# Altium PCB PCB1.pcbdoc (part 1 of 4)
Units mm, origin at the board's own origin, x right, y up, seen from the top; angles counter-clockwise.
Board outline 77.9 x 107.7 mm, 4 copper layers (Top Layer, Inner1, Inner2, Bottom Layer); 106 components, 123 nets, 650 pads, 272 vias.
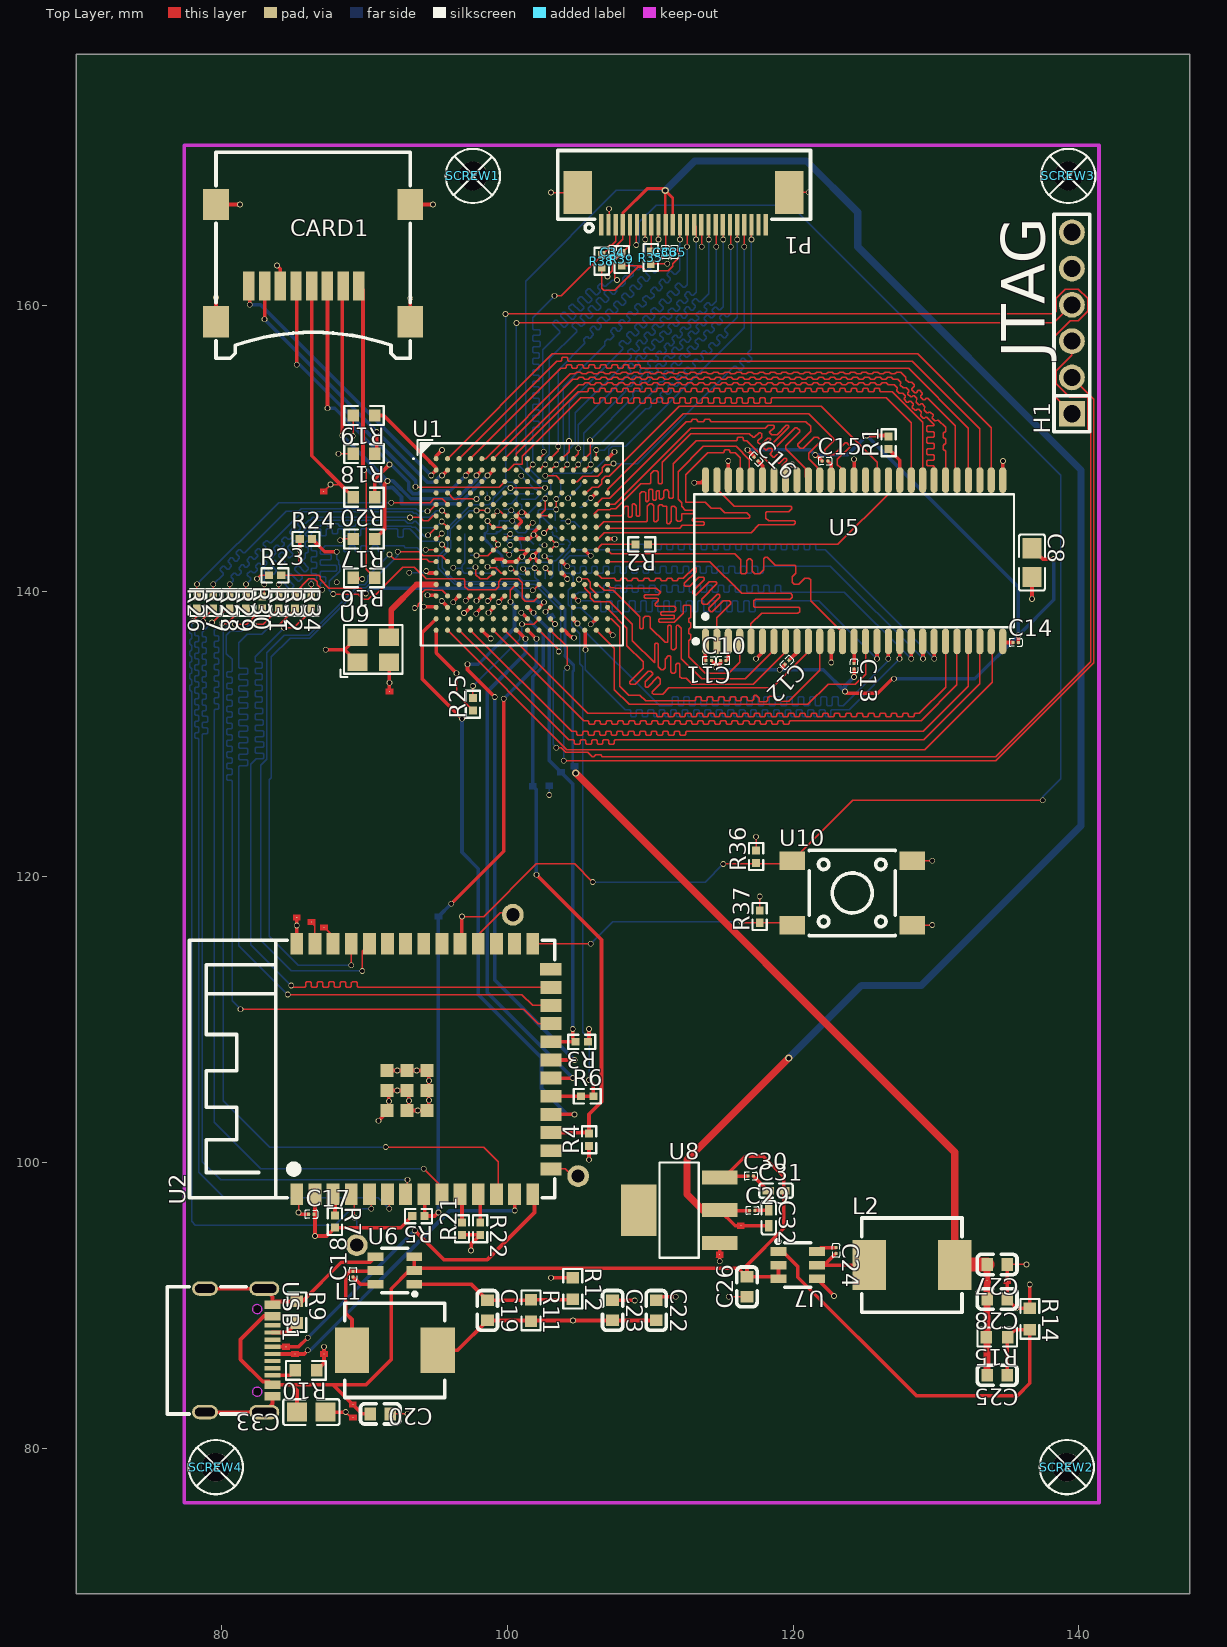
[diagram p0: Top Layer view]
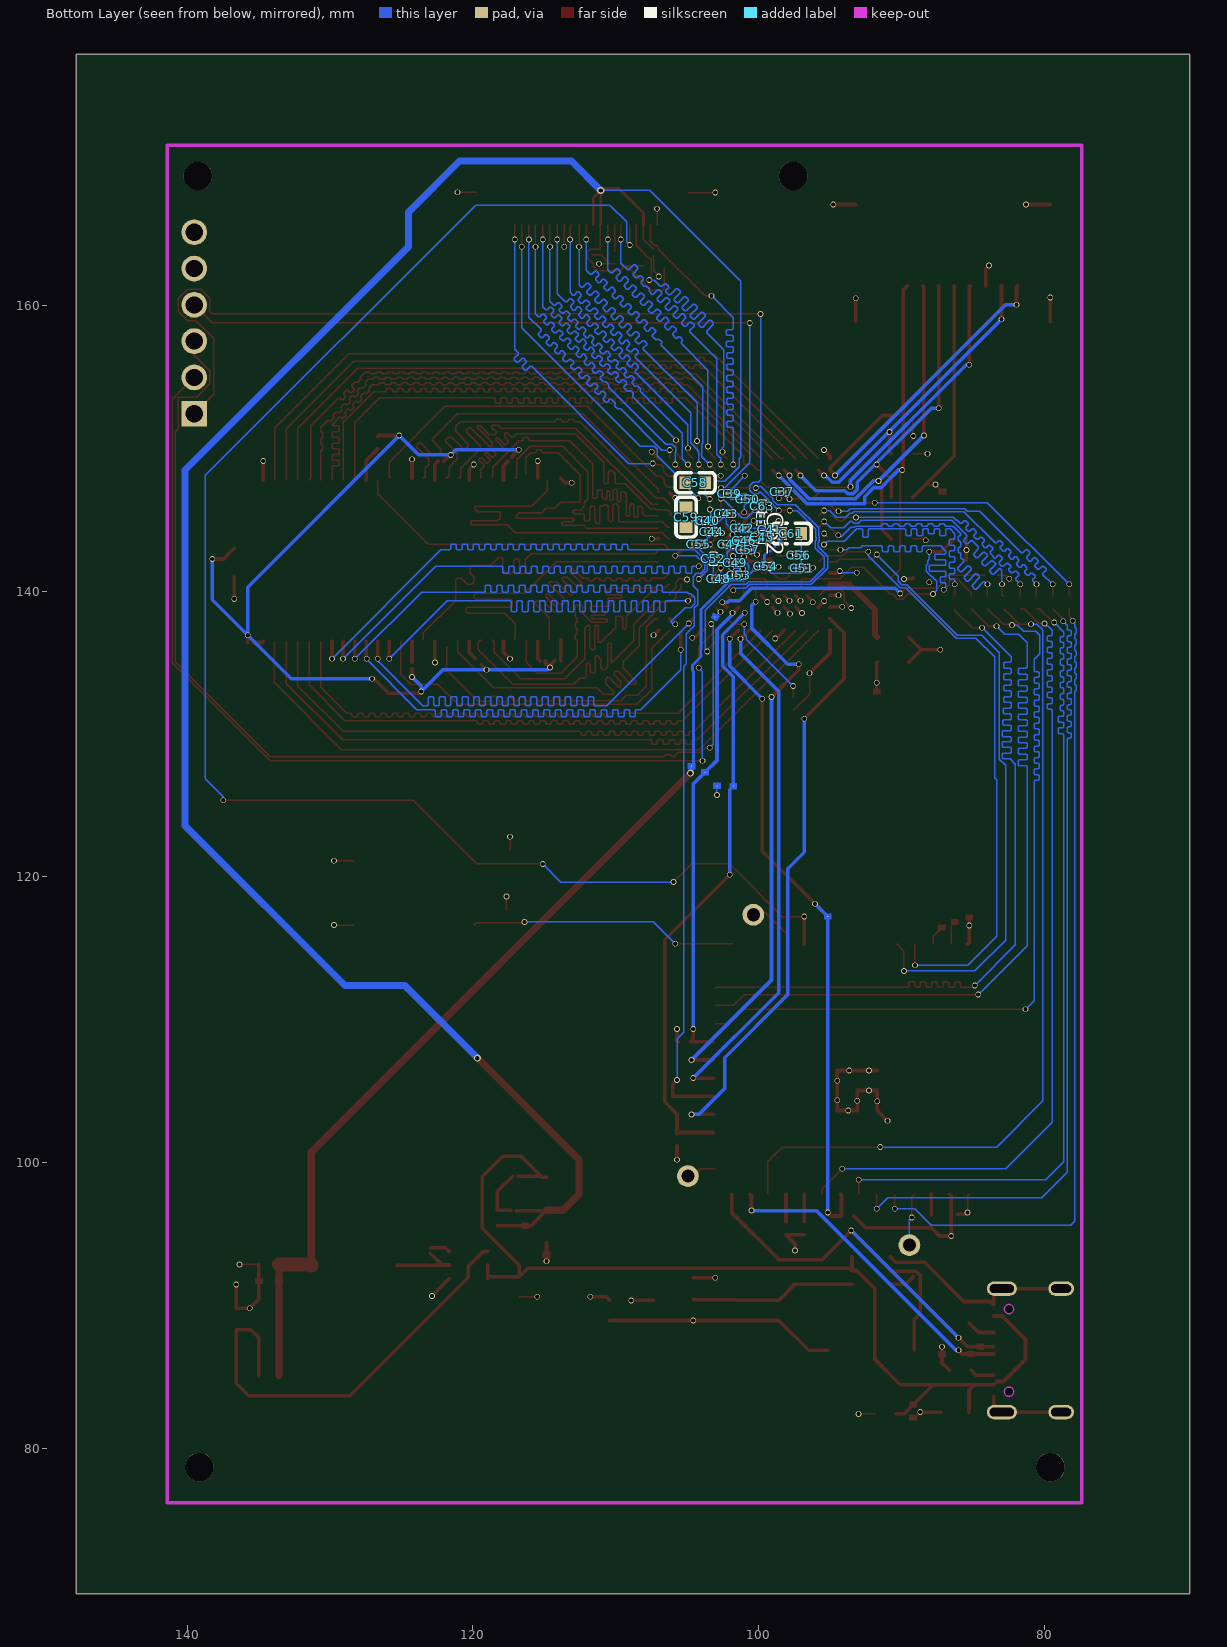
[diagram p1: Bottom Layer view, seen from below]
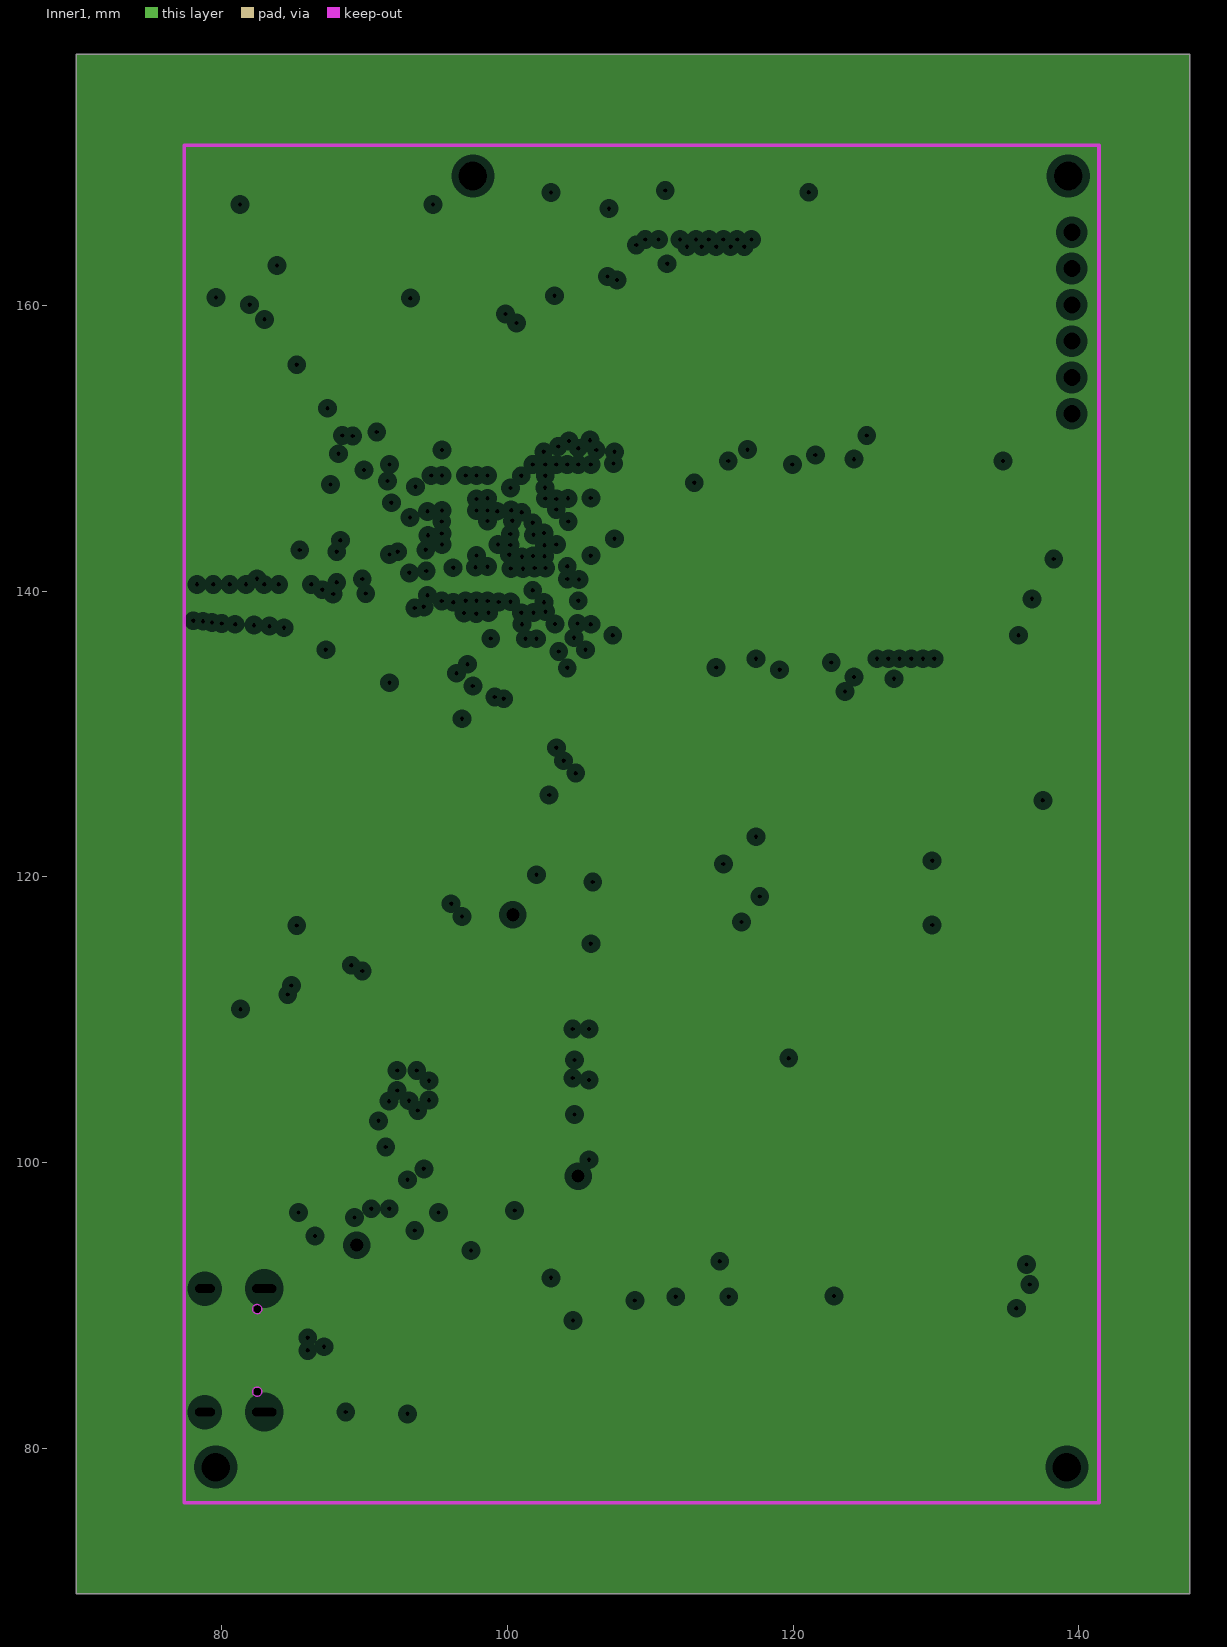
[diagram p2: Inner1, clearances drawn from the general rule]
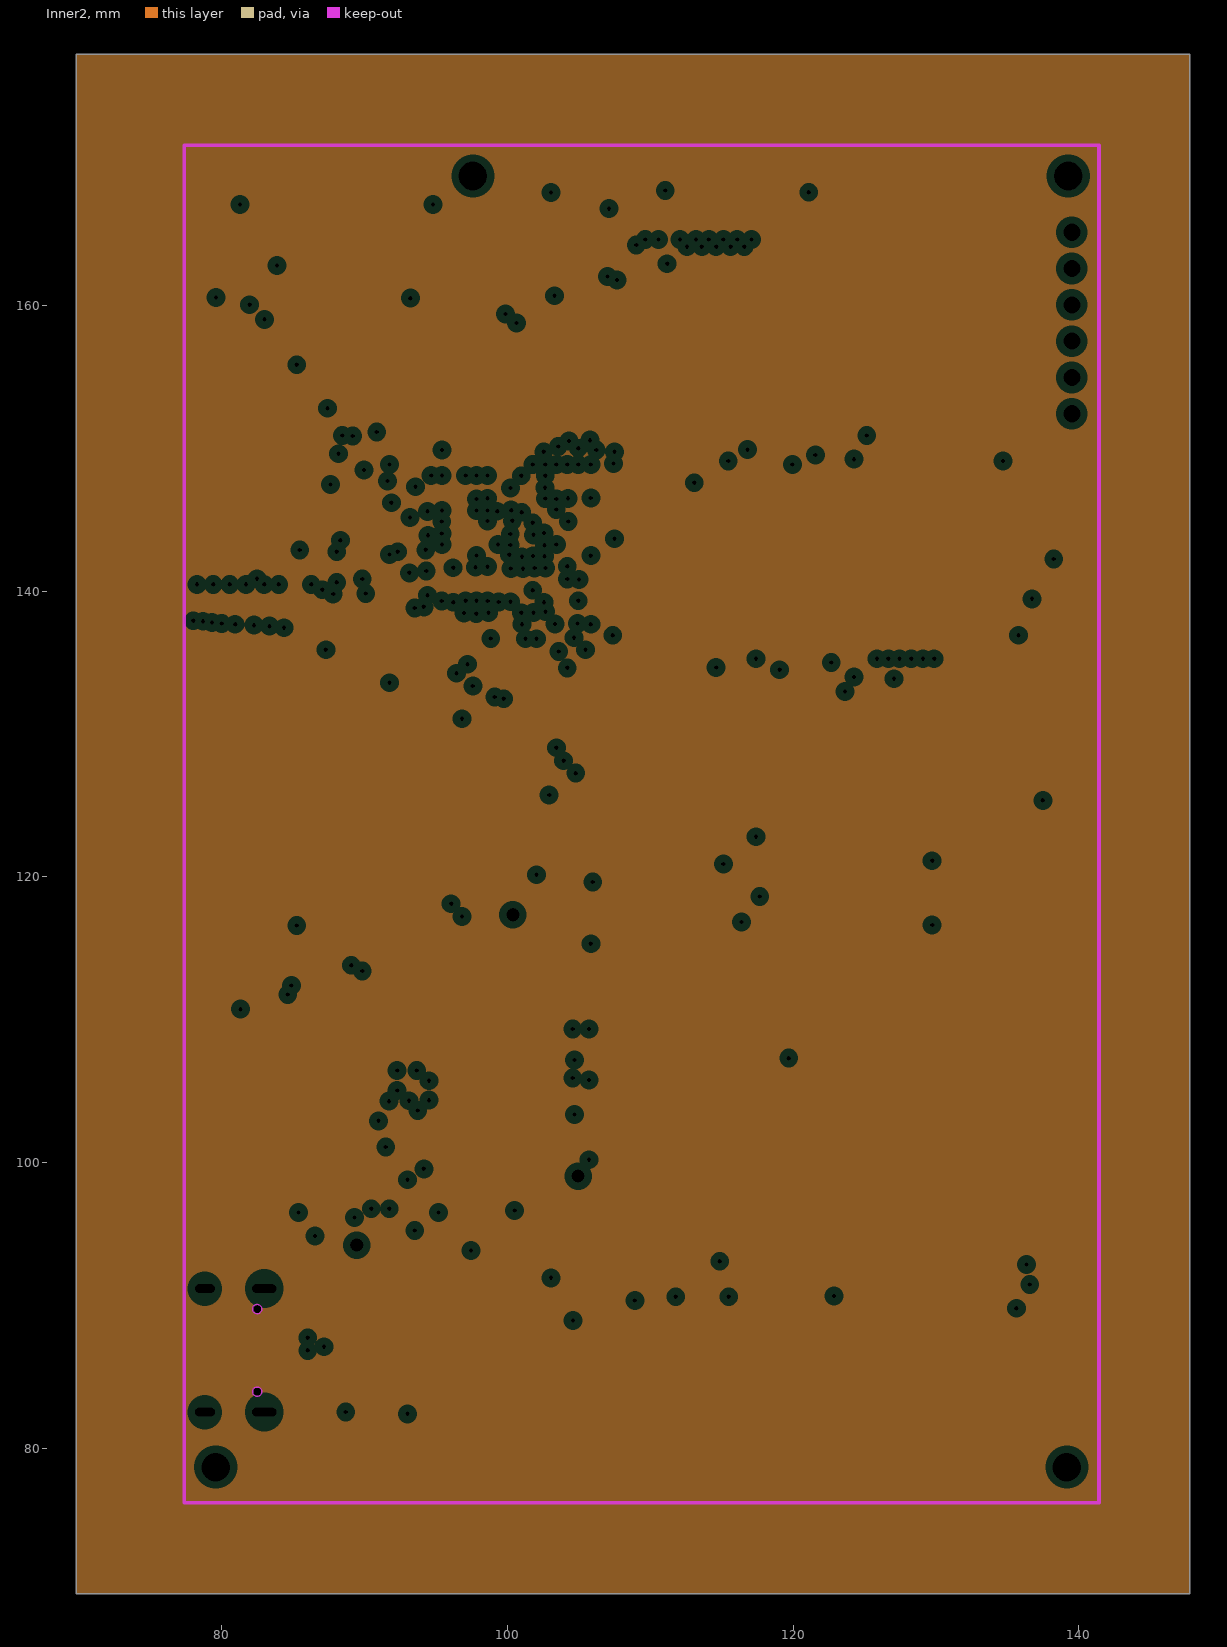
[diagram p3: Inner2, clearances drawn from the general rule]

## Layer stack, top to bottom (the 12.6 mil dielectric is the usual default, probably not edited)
Top Layer: signal copper (thickness not stored)
Dielectric: dielectric 0.32, FR-4, Dk 4.8
Inner1: plane copper (thickness not stored)
Dielectric: dielectric 0.32, FR-4, Dk 4.8
Inner2: plane copper (thickness not stored)
Dielectric: dielectric 0.32, FR-4, Dk 4.8
Bottom Layer: signal copper (thickness not stored)

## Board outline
147.752,69.85 69.85,69.85 69.85,177.55 147.752,177.55

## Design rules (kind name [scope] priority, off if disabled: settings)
BoardOutlineClearance copperThickness1oz [All] p0: genericclearance=0.254 ignorepadtopadclearanceinfootprint=FALSE except(0: Arc-SplitContinuation Track-SplitContinuation SMDPad-SplitContinuation THPad-SplitContinuation Via-SplitContinuation Fill-SplitContinuation Poly-SplitContinuation Region-SplitContinuation Text-SplitContinuation; 0.152: Track-CutoutEdge SMDPad-CutoutEdge THPad-CutoutEdge Via-CutoutEdge Region-CutoutEdge; 0.3: Track-OutlineEdge SMDPad-OutlineEdge THPad-OutlineEdge Via-OutlineEdge Fill-OutlineEdge Region-OutlineEdge Poly-OutlineEdge Text-OutlineEdge Fill-CutoutEdge)
BoardOutlineClearance copperThickness2oz [All] p0: genericclearance=0.254 ignorepadtopadclearanceinfootprint=FALSE except(0: Arc-SplitContinuation Track-SplitContinuation SMDPad-SplitContinuation THPad-SplitContinuation Via-SplitContinuation Fill-SplitContinuation Poly-SplitContinuation Region-SplitContinuation Text-SplitContinuation; 0.152: Track-CutoutEdge SMDPad-CutoutEdge THPad-CutoutEdge Via-CutoutEdge Region-CutoutEdge; 0.3: Track-OutlineEdge SMDPad-OutlineEdge THPad-OutlineEdge Via-OutlineEdge Fill-OutlineEdge Region-OutlineEdge Poly-OutlineEdge Text-OutlineEdge Fill-CutoutEdge)
Clearance copperThickness1oz [(InNet('SD_A0') OR InNet('SD_A1') OR InNet('SD_A2') OR InNet('SD_A3') OR InNet('SD_A4') OR InNet('SD_A5') OR InNet('SD_A6') OR InNet('SD_A7') OR InNet('SD_A8') OR InNet('SD_A9') OR InNet('SD_A10') OR InNet('SD_A11') OR InNet('SD_A12') OR InNet('SD_DQ15') OR InNet('SD_DQ14') OR InNet('SD_DQ8') OR InNet('SD_BA0') OR InNet('SD_BA1') OR InNet('SD_DQ9') OR InNet('SD_DQ7') OR InNet('SD_CLK') OR InNet('SD_WE_N') OR InNet('SD_DQ10') OR InNet('SD_CAS_N') OR InNet('SD_DQM1') OR InNet('SD_DQ2') OR InNet('SD_DQ3') OR InNet('SD_DQ11') OR InNet('SD_DQ12') OR InNet('SD_DQ13') OR InNet('SD_DQ0') OR InNet('SD_DQ1') OR InNet('SD_CS_N') OR InNet('SD_RAS_N') OR InNet('SD_DQ4') OR InNet('SD_DQ6') OR InNet('$1N9241') OR InNet('$1N9192') OR InNet('GND') OR InNet('$1N9142') OR InNet('SD_DQ5') OR InNet('$1N9091') OR InNet('SD_DQM0') OR InNet('$1N9039') OR InNet('$1N8986') OR InNet('$1N8318') OR InNet('$1N9437') OR InNet('$1N9341') OR InNet('+3V3') OR InNet('$1N11348') OR InNet('DOUT') OR InNet('DIN') OR InNet('CCLK') OR InNet('DONE') OR InNet('PROGRAMN') OR InNet('INITN') OR InNet('$1N11975') OR InNet('DN') OR InNet('DP') OR InNet('$1N14459') OR InNet('$1N14416') OR InNet('$1N14567') OR InNet('+5V') OR InNet('$1N16833') OR InNet('$1N16832') OR InNet('+1V1') OR InNet('$1N16834') OR InNet('+1V8') OR InNet('$1N17349') OR InNet('$1N12557') OR InNet('$1N12553') OR InNet('M_D2') OR InNet('M_D3') OR InNet('M_CMD') OR InNet('M_CLK') OR InNet('M_D0') OR InNet('M_D1') OR InNet('SDA') OR InNet('SCL') OR InNet('RESET') OR InNet('VSYNC') OR InNet('HREF') OR InNet('Y9') OR InNet('MCLK') OR InNet('Y8') OR InNet('Y7') OR InNet('PCLK') OR InNet('Y6') OR InNet('Y2') OR InNet('Y5') OR InNet('Y3') OR InNet('Y4') OR InNet('CRYSTAL') OR InNet('SSPI_CS_N') OR InNet('D0') OR InNet('D1') OR InNet('D2') OR InNet('D4') OR InNet('D3') OR InNet('D5') OR InNet('D6') OR InNet('D7') OR InNet('RX') OR InNet('TX') OR InNet('$1N29790') OR InNet('$1N29833') OR InNet('$1N29916') OR InNet('$1N29959') OR InNet('$1N30002') OR InNet('$1N30085') OR InNet('$1N30089') OR InNet('$1N30093') OR InNet('TDO') OR InNet('TDI') OR InNet('TMS') OR InNet('TCK') OR InNet('$1N33205') OR InNet('PROGRAM') OR InNet('$2N5507') OR InNet('$2N5509') OR InNet('$2N5511') OR InNet('FSDA') OR InNet('FSCL'))] p1: gap=0.178 ignorepadtopadclearanceinfootprint=FALSE except(0.099: Track-Track; 0.152: Track-SMDPad SMDPad-SMDPad Track-THPad SMDPad-THPad THPad-THPad Track-Via SMDPad-Via THPad-Via Via-Via SMDPad-Fill THPad-Fill Via-Fill Fill-Fill Track-Region SMDPad-Region THPad-Region Via-Region Region-Region Track-Poly SMDPad-Poly THPad-Poly Via-Poly Fill-Poly Region-Poly Poly-Poly Track-Text SMDPad-Text THPad-Text Via-Text Fill-Text Region-Text Poly-Text Text-Text; 0.175: Track-Hole SMDPad-Hole THPad-Hole Via-Hole Fill-Hole Region-Hole Poly-Hole Text-Hole Sheet-Hole; 0.3: Track-Fill Fill-Region Track-Sheet SMDPad-Sheet THPad-Sheet Via-Sheet Fill-Sheet Region-Sheet Poly-Sheet Text-Sheet)
Clearance copperThickness2oz [All] p1: gap=0.178 ignorepadtopadclearanceinfootprint=FALSE except(0.152: Track-SMDPad SMDPad-SMDPad Track-THPad SMDPad-THPad THPad-THPad Track-Via SMDPad-Via THPad-Via Via-Via SMDPad-Fill THPad-Fill Via-Fill Fill-Fill Track-Region SMDPad-Region THPad-Region Via-Region Region-Region Track-Poly SMDPad-Poly THPad-Poly Via-Poly Fill-Poly Region-Poly Poly-Poly Track-Text SMDPad-Text THPad-Text Via-Text Fill-Text Region-Text Poly-Text Text-Text; 0.175: Track-Hole SMDPad-Hole THPad-Hole Via-Hole Fill-Hole Region-Hole Poly-Hole Text-Hole Sheet-Hole; 0.203: Track-Track; 0.3: Track-Fill Fill-Region Track-Sheet SMDPad-Sheet THPad-Sheet Via-Sheet Fill-Sheet Region-Sheet Poly-Sheet Text-Sheet)
DiffPairsRouting differentialPair [All] p1: maxuncoupledlength=10 minlimit=6 maxlimit=6 mostfreqgap=6 toplayer_minwidth=5 toplayer_prefwidth=10 toplayer_maxwidth=100 bottomlayer_minwidth=5 bottomlayer_prefwidth=10 bottomlayer_maxwidth=100
PasteMaskExpansion pasteMaskExpansion [All] p1: expansion=0
PlaneConnect innerPlane [All] p1: planeconnectstyle=Relief reliefexpansion=0.508 reliefentries=4 reliefconductorwidth=0.254 reliefairgap=0.254
PolygonConnect copperRegion [All] p1: connectstyle=Relief reliefentries=4 reliefconductorwidth=10 polygonreliefangle="90 Angle" airgapwidth=10
RoutingVias viaSize [All] p1: viastyle="Through Hole" holewidth=11.811 minholewidth=11.811 maxholewidth=248.0314 width=15.748 minwidth=15.748 maxwidth=393.7008
SolderMaskExpansion solderMaskExpansion [All] p1: useseparateexpansions=TRUE expansion=2 expansionbottom=2
Width copperThickness1oz [All] p1: maxlimit=100 minlimit=4 preferedwidth=4
Width copperThickness2oz [All] p1: maxlimit=100 minlimit=8 preferedwidth=10

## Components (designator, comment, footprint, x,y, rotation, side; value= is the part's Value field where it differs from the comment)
C8 "CL21A476MQYNNNE" C0805 136.711,141.99 r270 top
C10 "GRM022R60J104KE15D" C01005 114.105,135.132 r0 top
C11 "GRM022R60J104KE15D" C01005 115.121,135.132 r180 top
C12 "GRM022R60J104KE15D" C01005 119.566,135.005 r225 top
C13 "GRM022R60J104KE15D" C01005 124.265,134.751 r270 top
C14 "GRM022R60J104KE15D" C01005 135.568,136.402 r0 top
C15 "GRM022R60J104KE15D" C01005 122.233,149.102 r0 top
C16 "GRM022R60J104KE15D" C01005 117.407,149.229 r315 top
C17 "GRM022R60J104KE15D" C01005 86.292,96.397 r0 top
C18 "GRM022R60J104KE15D" C01005 89.213,92.206 r90 top
C19 "TCC0603X7R104K500CT" C0603 98.611,89.666 r270 top
C20 "TCC0603X5R226M6R3CT" C0603 91.118,82.427 r180 top
C22 "TCC0603X5R226M6R3CT" C0603 110.422,89.666 r270 top
C23 "TCC0603X5R226M6R3CT" C0603 107.374,89.666 r270 top
C24 "GRM022R60J104KE15D" C01005 122.995,93.857 r270 top
C25 "TCC0603X7R104K500CT" C0603 134.277,85.133 r180 top
C26 "TCC0603X5R226M6R3CT" C0603 116.772,91.317 r90 top
C27 "TCC0603X5R226M6R3CT" C0603 134.277,92.88 r180 top
C28 "TCC0603X5R226M6R3CT" C0603 134.277,90.467 r180 top
C29 "GRM022R60J104KE15D" C01005 117.153,96.651 r0 top
C30 "GRM022R60J104KE15D" C01005 117.026,99.064 r0 top
C31 "GRM155R60J106ME44D" C0402 118.804,98.048 r0 top
C32 "GRM155R60J106ME44D" C0402 118.296,96.143 r270 top
C33 "CL21A476MQYNNNE" C0805 86.292,82.554 r180 top
C34 "GRM022R60J104KE15D" C01005 107.374,163.707 r270 top
C35 "GRM022R60J104KE15D" C01005 111.692,163.707 r270 top
C36 "GRM022R60J104KE15D" C01005 111.057,163.707 r270 top
C37 "GRM022R60J104KE15D" C01005 98.357,146.943 r180 bottom
C39 "GRM022R60J104KE15D" C01005 102.04,146.816 r180 bottom
C40 "GRM022R60J104KE15D" C01005 103.564,144.911 r180 bottom
C41 "GRM022R60J104KE15D" C01005 99.246,144.276 r90 bottom
C42 "GRM022R60J104KE15D" C01005 101.151,144.403 r180 bottom
C43 "GRM022R60J104KE15D" C01005 102.294,145.419 r180 bottom
C44 "GRM022R60J104KE15D" C01005 103.31,144.149 r180 bottom
C45 "GRM022R60J104KE15D" C01005 99.754,143.768 r270 bottom
C46 "GRM022R60J104KE15D" C01005 101.024,143.514 r180 bottom
C47 "GRM022R60J104KE15D" C01005 102.04,143.26 r0 bottom
C48 "GRM022R60J104KE15D" C01005 102.802,140.847 r0 bottom
C49 "GRM022R60J104KE15D" C01005 101.659,141.99 r180 bottom
C50 "GRM022R60J104KE15D" C01005 100.77,146.435 r180 bottom
C51 "GRM022R60J104KE15D" C01005 96.96,141.609 r180 bottom
C52 "GRM022R60J104KE15D" C01005 103.183,142.244 r270 bottom
C53 "GRM022R60J104KE15D" C01005 101.405,141.101 r180 bottom
C54 "GRM022R60J104KE15D" C01005 99.5,141.736 r180 bottom
C55 "GRM022R60J104KE15D" C01005 104.199,143.26 r0 bottom
C56 "GRM022R60J104KE15D" C01005 97.214,142.498 r180 bottom
C57 "GRM022R60J104KE15D" C01005 100.77,142.879 r0 bottom
C58 "TCC0603X5R226M6R3CT" C0603 104.453,147.578 r180 bottom
C59 "TCC0603X5R226M6R3CT" C0603 105.088,145.165 r90 bottom
C61 "TCC0603X5R226M6R3CT" C0603 97.722,144.022 r180 bottom
C62 "GRM022R60J104KE15D" C01005 99.881,145.038 r270 bottom
C63 "GRM022R60J104KE15D" C01005 99.754,145.927 r90 bottom
CARD1 "DS1139-06-08SS4BSR" TF-SMD_DS1139-06-08SS4BSR 86.419,162.945 r0 top
H1 "2.54-1x6P直针" HDR-TH_6P-P2.54-V-M-1 139.505,158.754 r90 top
L1 "FXL0630-6R8-M" IND-SMD_L7.0-W6.6 92.134,86.872 r0 top
L2 "FXL0630-100-M" IND-SMD_L7.3-W6.8 128.313,92.835 r0 top
P1 "AFC07-S24FCC-00" FPC-SMD_AFC07-S24FCC-00 112.327,166.755 r180 top
R1 "0402WGF1002TCE" R0402 126.678,150.372 r90 top
R2 "0402WGF330JTCE" R0402 109.406,143.26 r180 top
R3 "0402WGF1002TCE" R0402 105.215,108.462 r180 top
R4 "0402WGF1002TCE" R0402 105.723,101.604 r90 top
R5 "0402WGF1002TCE" R0402 93.785,96.27 r180 top
R6 "0402WGF330JTCE" R0402 105.596,104.652 r0 top
R7 "0402WGF1002TCE" R0402 87.943,95.889 r270 top
R9 "0603WAF5101T5E" R0603 85.276,89.539 r270 top
R10 "0603WAF5101T5E" R0603 85.911,85.475 r180 top
R11 "FRC0603F1963TS" R0603 101.659,89.666 r270 top
R12 "FRC0603F6202TS" R0603 104.58,91.19 r270 top
R14 "FRC0603F6202TS" R0603 136.563,89.07 r270 top
R15 "0603WAF2322T5E" R0603 134.277,87.8 r180 top
R16 "FRC0603F6202TS" R0603 89.971,140.923 r180 top
R17 "FRC0603F6202TS" R0603 89.975,143.641 r180 top
R18 "FRC0603F6202TS" R0603 89.975,149.61 r180 top
R19 "FRC0603F6202TS" R0603 89.975,152.277 r180 top
R20 "FRC0603F6202TS" R0603 89.975,146.562 r180 top
R21 "0402WGF1002TCE" R0402 96.833,95.381 r270 top
R22 "0402WGF1002TCE" R0402 98.103,95.381 r270 top
R23 "0402WGF1002TCE" R0402 83.752,141.101 r0 top
R24 "0402WGF1002TCE" R0402 85.911,143.641 r0 top
R25 "0402WGF1002TCE" R0402 97.595,132.084 r90 top
R26 "0402WGF330JTCE" R0402 78.291,139.196 r270 top
R27 "0402WGF330JTCE" R0402 79.434,139.196 r270 top
R28 "0402WGF330JTCE" R0402 80.577,139.196 r270 top
R29 "0402WGF330JTCE" R0402 81.72,139.196 r270 top
R30 "0402WGF330JTCE" R0402 82.863,139.196 r270 top
R31 "0402WGF330JTCE" R0402 84.006,139.196 r270 top
R32 "0402WGF330JTCE" R0402 85.149,139.196 r270 top
R34 "0402WGF330JTCE" R0402 86.292,139.196 r270 top
R35 "0402WGF1002TCE" R0402 110.041,163.326 r270 top
R36 "0402WGF1002TCE" R0402 117.407,121.416 r90 top
R37 "0402WGF1002TCE" R0402 117.661,117.225 r90 top
R38 "0402WGF1002TCE" R0402 106.612,163.072 r270 top
R39 "0402WGF1002TCE" R0402 108.009,163.199 r270 top
SCREW1 "Screw-Hole-M2" Screw-Hole-M2 97.595,169.041 r0 top
SCREW2 "Screw-Hole-M2" Screw-Hole-M2 139.151,78.702 r0 top
SCREW3 "Screw-Hole-M2" Screw-Hole-M2 139.251,169.041 r0 top
SCREW4 "Screw-Hole-M2" Screw-Hole-M2 79.603,78.702 r0 top
U1 "LFE5U-25F-6BG256C" CABGA-256_L14.0-W14.0-R16-C16-P0.80-TL 101.024,143.26 r0 top
U2 "ESP32-S3-WROOM-1-N16R2" WIRELM-SMD_ESP32-S3-WROOM-1 94.166,106.557 r90 top
U5 "W9825G6KH-6" TSOP-54_L22.2-W10.2-P0.80-LS11.8-BL 124.265,142.117 r0 top
U6 "AP63200WU-7" SOT-23-6_L2.9-W1.6-P0.95-LS2.8-BR 92.134,92.46 r0 top
U7 "AP63200WU-7" SOT-23-6_L2.9-W1.6-P0.95-LS2.8-BR 120.328,92.841 r180 top
U8 "AMS1117-1.8_C6185" SOT-223-4_L6.5-W3.5-P2.30-LS7.0-BR 112.026,96.68 r0 top
U9 "XOS32024000LT00351005" OSC-SMD_4P-L3.2-W2.5-BL 90.61,135.894 r0 top
U10 "TPS645-5NC60" SW-SMD_4P-L6.0-W6.0-P4.50-LS9.2 124.138,118.876 r0 top
USB1 "TYPE-C16PIN" USB-C-SMD_TYPE-C16PIN 81.212,86.872 r270 top

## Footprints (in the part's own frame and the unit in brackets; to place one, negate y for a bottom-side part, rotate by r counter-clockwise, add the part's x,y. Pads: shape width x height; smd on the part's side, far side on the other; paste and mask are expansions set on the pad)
C0402 [mm]
  rect 0.79x0.54 smd: 1(-0.545,0) 2(0.545,0)
  silkscreen extent -1.17,-0.5 1.17,0.5
C0603 [mm]
  rect 0.8x0.9 smd: 1(-0.7,0) 2(0.7,0)
  silkscreen extent -1.39,-0.71 1.39,0.71
C0805 [mm]
  rect 1.41x1.35 smd: 1(-1,0) 2(1,0)
  silkscreen extent -1.96,-0.9 1.96,0.9
C01005 [mm]
  rect 0.21x0.22 smd: 1(-0.195,0) 2(0.195,0)
  silkscreen extent -0.46,-0.27 0.46,0.27
CABGA-256_L14.0-W14.0-R16-C16-P0.80-TL [mm]
  round 0.36 smd: A1(-6,6) A2(-5.2,6) A3(-4.4,6) A4(-3.6,6) A5(-2.8,6) A6(-2,6) A7(-1.2,6) A8(-0.4,6) A9(0.4,6) A10(1.2,6) A11(2,6) A12(2.8,6) A13(3.6,6) A14(4.4,6) A15(5.2,6) A16(6,6) B1(-6,5.2) B2(-5.2,5.2) B3(-4.4,5.2) B4(-3.6,5.2) B5(-2.8,5.2) B6(-2,5.2) B7(-1.2,5.2) B8(-0.4,5.2) B9(0.4,5.2) B10(1.2,5.2) B11(2,5.2) B12(2.8,5.2) B13(3.6,5.2) B14(4.4,5.2) B15(5.2,5.2) B16(6,5.2) C1(-6,4.4) C2(-5.2,4.4) C3(-4.4,4.4) C4(-3.6,4.4) C5(-2.8,4.4) C6(-2,4.4) C7(-1.2,4.4) C8(-0.4,4.4) C9(0.4,4.4) C10(1.2,4.4) C11(2,4.4) C12(2.8,4.4) C13(3.6,4.4) C14(4.4,4.4) C15(5.2,4.4) C16(6,4.4) D1(-6,3.6) D2(-5.2,3.6) D3(-4.4,3.6) D4(-3.6,3.6) D5(-2.8,3.6) D6(-2,3.6) D7(-1.2,3.6) D8(-0.4,3.6) D9(0.4,3.6) D10(1.2,3.6) D11(2,3.6) D12(2.8,3.6) D13(3.6,3.6) D14(4.4,3.6) D15(5.2,3.6) D16(6,3.6) E1(-6,2.8) E2(-5.2,2.8) E3(-4.4,2.8) E4(-3.6,2.8) E5(-2.8,2.8) E6(-2,2.8) E7(-1.2,2.8) E8(-0.4,2.8) E9(0.4,2.8) E10(1.2,2.8) E11(2,2.8) E12(2.8,2.8) E13(3.6,2.8) E14(4.4,2.8) E15(5.2,2.8) E16(6,2.8) F1(-6,2) F2(-5.2,2) F3(-4.4,2) F4(-3.6,2) F5(-2.8,2) F6(-2,2) F7(-1.2,2) F8(-0.4,2) F9(0.4,2) F10(1.2,2) F11(2,2) F12(2.8,2) F13(3.6,2) F14(4.4,2) F15(5.2,2) F16(6,2) G1(-6,1.2) G2(-5.2,1.2) G3(-4.4,1.2) G4(-3.6,1.2) G5(-2.8,1.2) G6(-2,1.2) G7(-1.2,1.2) G8(-0.4,1.2) G9(0.4,1.2) G10(1.2,1.2) G11(2,1.2) G12(2.8,1.2) G13(3.6,1.2) G14(4.4,1.2) G15(5.2,1.2) G16(6,1.2) H1(-6,0.4) H2(-5.2,0.4) H3(-4.4,0.4) H4(-3.6,0.4) H5(-2.8,0.4) H6(-2,0.4) H7(-1.2,0.4) H8(-0.4,0.4) H9(0.4,0.4) H10(1.2,0.4) H11(2,0.4) H12(2.8,0.4) H13(3.6,0.4) H14(4.4,0.4) H15(5.2,0.4) H16(6,0.4) J1(-6,-0.4) J2(-5.2,-0.4) J3(-4.4,-0.4) J4(-3.6,-0.4) J5(-2.8,-0.4) J6(-2,-0.4) J7(-1.2,-0.4) J8(-0.4,-0.4) J9(0.4,-0.4) J10(1.2,-0.4) J11(2,-0.4) J12(2.8,-0.4) J13(3.6,-0.4) J14(4.4,-0.4) J15(5.2,-0.4) J16(6,-0.4) K1(-6,-1.2) K2(-5.2,-1.2) K3(-4.4,-1.2) K4(-3.6,-1.2) K5(-2.8,-1.2) K6(-2,-1.2) K7(-1.2,-1.2) K8(-0.4,-1.2) K9(0.4,-1.2) K10(1.2,-1.2) K11(2,-1.2) K12(2.8,-1.2) K13(3.6,-1.2) K14(4.4,-1.2) K15(5.2,-1.2) K16(6,-1.2) L1(-6,-2) L2(-5.2,-2) L3(-4.4,-2) L4(-3.6,-2) L5(-2.8,-2) L6(-2,-2) L7(-1.2,-2) L8(-0.4,-2) L9(0.4,-2) L10(1.2,-2) L11(2,-2) L12(2.8,-2) L13(3.6,-2) L14(4.4,-2) L15(5.2,-2) L16(6,-2) M1(-6,-2.8) M2(-5.2,-2.8) M3(-4.4,-2.8) M4(-3.6,-2.8) M5(-2.8,-2.8) M6(-2,-2.8) M7(-1.2,-2.8) M8(-0.4,-2.8) M9(0.4,-2.8) M10(1.2,-2.8) M11(2,-2.8) M12(2.8,-2.8) M13(3.6,-2.8) M14(4.4,-2.8) M15(5.2,-2.8) M16(6,-2.8) N1(-6,-3.6) N2(-5.2,-3.6) N3(-4.4,-3.6) N4(-3.6,-3.6) N5(-2.8,-3.6) N6(-2,-3.6) N7(-1.2,-3.6) N8(-0.4,-3.6) N9(0.4,-3.6) N10(1.2,-3.6) N11(2,-3.6) N12(2.8,-3.6) N13(3.6,-3.6) N14(4.4,-3.6) N15(5.2,-3.6) N16(6,-3.6) P1(-6,-4.4) P2(-5.2,-4.4) P3(-4.4,-4.4) P4(-3.6,-4.4) P5(-2.8,-4.4) P6(-2,-4.4) P7(-1.2,-4.4) P8(-0.4,-4.4) P9(0.4,-4.4) P10(1.2,-4.4) P11(2,-4.4) P12(2.8,-4.4) P13(3.6,-4.4) P14(4.4,-4.4) P15(5.2,-4.4) P16(6,-4.4) R1(-6,-5.2) R2(-5.2,-5.2) R3(-4.4,-5.2) R4(-3.6,-5.2) R5(-2.8,-5.2) R6(-2,-5.2) R7(-1.2,-5.2) R8(-0.4,-5.2) R9(0.4,-5.2) R10(1.2,-5.2) R11(2,-5.2) R12(2.8,-5.2) R13(3.6,-5.2) R14(4.4,-5.2) R15(5.2,-5.2) R16(6,-5.2) T1(-6,-6) T2(-5.2,-6) T3(-4.4,-6) T4(-3.6,-6) T5(-2.8,-6) T6(-2,-6) T7(-1.2,-6) T8(-0.4,-6) T9(0.4,-6) T10(1.2,-6) T11(2,-6) T12(2.8,-6) T13(3.6,-6) T14(4.4,-6) T15(5.2,-6) T16(6,-6)
  silkscreen extent -7.63,-7.08 7.08,7.3
FPC-SMD_AFC07-S24FCC-00 [mm]
  rect 0.3x1.5 smd: 1(5.745,1.129) 2(5.245,1.129) 3(4.746,1.129) 4(4.245,1.129) 5(3.746,1.129) 6(3.245,1.129) 7(2.746,1.129) 8(2.245,1.129) 9(1.746,1.129) 10(1.245,1.129) 11(0.746,1.129) 12(0.245,1.129) 13(-0.254,1.129) 14(-0.755,1.129) 15(-1.251,1.13) 16(-1.754,1.13) 17(-2.254,1.128) 18(-2.754,1.129) 19(-3.254,1.129) 20(-3.756,1.132) 21(-4.256,1.132) 22(-4.756,1.132) 23(-5.256,1.132) 24(-5.756,1.132)
  rect 2x3 smd: 25(-7.401,-1.132) 26(7.401,-1.125)
  silkscreen extent -8.89,-4.07 8.8,1.61
HDR-TH_6P-P2.54-V-M-1 [mm]
  rect 1.8x1.8 hole 1.2: 1(-6.35,0)
  round 1.8 hole 1.2: 2(-3.81,0) 3(-1.27,0) 4(1.27,0) 5(3.81,0) 6(6.35,0)
  silkscreen extent -7.62,-1.25 7.62,1.25
IND-SMD_L7.0-W6.6 [mm]
  rect 2.4x3.2 smd: 1(-3,0) 2(3,0)
  silkscreen extent -3.5,-3.3 3.5,3.3
IND-SMD_L7.3-W6.8 [mm]
  rect 2.35x3.5 smd: 1(-3,0) 2(3,0)
  silkscreen extent -3.5,-3.3 3.5,3.3
OSC-SMD_4P-L3.2-W2.5-BL [mm]
  rect 1.4x1.2 smd: 1(-1.1,-0.875) 2(1.1,-0.875) 3(1.1,0.875) 4(-1.1,0.875)
  silkscreen extent -2.29,-1.9 2.07,1.72
R0402 [mm]
  rect 0.566x0.54 smd: 1(-0.433,0) 2(0.433,0)
  silkscreen extent -0.94,-0.5 0.94,0.5
R0603 [mm]
  rect 0.806x0.864 smd: 1(-0.753,0) 2(0.753,0)
  silkscreen extent -1.39,-0.66 1.39,0.66
Screw-Hole-M2 [mm]
  round 2 hole 2: 1(0,0)
  silkscreen extent -1.9,-1.9 1.9,1.9
SOT-23-6_L2.9-W1.6-P0.95-LS2.8-BR [mm]
  rect 1.1x0.6 smd: 1(1.35,-0.95) 2(1.35,0) 3(1.35,0.95) 4(-1.35,0.95) 5(-1.35,0) 6(-1.35,-0.95)
  silkscreen extent -0.9,-1.78 1.52,1.55
SOT-223-4_L6.5-W3.5-P2.30-LS7.0-BR [mm]
  rect 2.47x0.98 smd: 1(2.835,-2.3) 2(2.835,0) 3(2.835,2.3)
  rect 2.47x3.6 smd: 4(-2.835,0)
  silkscreen extent -1.37,-3.33 1.37,3.33
SW-SMD_4P-L6.0-W6.0-P4.50-LS9.2 [mm]
  rect 1.8x1.3 smd: 1(-4.2,2.25) 2(4.2,2.25) 3(-4.2,-2.25) 4(4.2,-2.25)
  silkscreen extent -3,-3 3,3
TF-SMD_DS1139-06-08SS4BSR [mm]
  rect 0.8x2 smd: 1(3.2,-1.6) 2(2.1,-1.6) 3(1,-1.6) 4(-0.1,-1.6) 5(-1.2,-1.6) 6(-2.3,-1.6) 7(-3.4,-1.6) 8(-4.5,-1.6)
  rect 1.8x2.2 smd: 9(-6.8,4.1) 10(-6.8,-4.1) 11(6.8,-4.1) 12(6.8,4.1)
  silkscreen extent -6.8,-6.65 6.8,7.75
TSOP-54_L22.2-W10.2-P0.80-LS11.8-BL [mm]
  oval 0.5x1.8 smd: 1(-10.4,-5.642) 2(-9.6,-5.642) 3(-8.8,-5.642) 4(-8,-5.642) 5(-7.2,-5.642) 6(-6.4,-5.642) 7(-5.6,-5.642) 8(-4.8,-5.642) 9(-4,-5.642) 10(-3.2,-5.642) 11(-2.4,-5.642) 12(-1.6,-5.642) 13(-0.8,-5.642) 14(0,-5.642) 15(0.8,-5.642) 16(1.6,-5.642) 17(2.4,-5.642) 18(3.2,-5.642) 19(4,-5.642) 20(4.8,-5.642) 21(5.6,-5.642) 22(6.4,-5.642) 23(7.2,-5.642) 24(8,-5.642) 25(8.8,-5.642) 26(9.6,-5.642) 27(10.4,-5.642) 28(10.4,5.642) 29(9.6,5.642) 30(8.8,5.642) 31(8,5.642) 32(7.2,5.642) 33(6.4,5.642) 34(5.6,5.642) 35(4.8,5.642) 36(4,5.642) 37(3.2,5.642) 38(2.4,5.642) 39(1.6,5.642) 40(0.8,5.642) 41(0,5.642) 42(-0.8,5.642) 43(-1.6,5.642) 44(-2.4,5.642) 45(-3.2,5.642) 46(-4,5.642) 47(-4.8,5.642) 48(-5.6,5.642) 49(-6.4,5.642) 50(-7.2,5.642) 51(-8,5.642) 52(-8.8,5.642) 53(-9.6,5.642) 54(-10.4,5.642)
  silkscreen extent -11.23,-5.79 11.19,4.65
USB-C-SMD_TYPE-C16PIN [mm]
  oval 1x2.1 hole 0.6 slot 1.7 at 90 deg: 1(-4.32,1.787) 2(4.32,1.787)
  oval 1x1.8 hole 0.6 slot 1.4 at 90 deg: 3(-4.32,-2.362) 4(4.32,-2.362)
  rect 0.6x1.15 smd: A1B12(-3.2,2.362) A4B9(-2.4,2.362) B1A12(3.2,2.362) B4A9(2.4,2.362)
  rect 0.3x1.15 smd: A5(-1.25,2.362) A6(-0.25,2.362) A7(0.25,2.362) A8(1.25,2.362) B5(1.75,2.362) B6(0.75,2.362) B7(-0.75,2.362) B8(-1.75,2.362)
  Board Outline Layer circle w0.005: c2.89,1.288 r0.325
  Board Outline Layer circle w0.005: c-2.89,1.288 r0.325
  Board Outline Layer region: 2.89,1.613 3.031,1.581 3.144,1.491 3.207,1.36 3.207,1.216 3.144,1.085 3.031,0.995 2.89,0.963 2.89,0.963 2.749,0.995 2.636,1.085 2.573,1.216 2.573,1.36 2.636,1.491 2.749,1.581 2.89,1.613
  Board Outline Layer region: -2.89,1.613 -2.749,1.581 -2.636,1.491 -2.573,1.36 -2.573,1.216 -2.636,1.085 -2.749,0.995 -2.89,0.963 -2.89,0.963 -3.031,0.995 -3.144,1.085 -3.207,1.216 -3.207,1.36 -3.144,1.491 -3.031,1.581 -2.89,1.613
  Multi-Layer board cut-out: 2.89,1.613 3.031,1.581 3.144,1.491 3.207,1.36 3.207,1.216 3.144,1.085 3.031,0.995 2.89,0.963 2.89,0.963 2.749,0.995 2.636,1.085 2.573,1.216 2.573,1.36 2.636,1.491 2.749,1.581 2.89,1.613
  Multi-Layer board cut-out: -2.89,1.613 -2.749,1.581 -2.636,1.491 -2.573,1.36 -2.573,1.216 -2.636,1.085 -2.749,0.995 -2.89,0.963 -2.89,0.963 -3.031,0.995 -3.144,1.085 -3.207,1.216 -3.207,1.36 -3.144,1.491 -3.031,1.581 -2.89,1.613
  silkscreen extent -4.45,-5 4.45,0.52
WIRELM-SMD_ESP32-S3-WROOM-1 [mm]
  rect 1.5x0.9 smd: 1(-8.75,8.895) 2(-8.75,7.625) 3(-8.75,6.355) 4(-8.75,5.085) 5(-8.75,3.815) 6(-8.75,2.545) 7(-8.75,1.275) 8(-8.75,0.005) 9(-8.75,-1.265) 10(-8.75,-2.535) 11(-8.75,-3.805) 12(-8.75,-5.075) 13(-8.75,-6.345) 14(-8.75,-7.615) 27(8.75,-7.615) 28(8.75,-6.345) 29(8.75,-5.075) 30(8.75,-3.805) 31(8.75,-2.535) 32(8.75,-1.265) 33(8.75,0.005) 34(8.75,1.275) 35(8.75,2.545) 36(8.75,3.815) 37(8.75,5.085) 38(8.75,6.355) 39(8.75,7.625) 40(8.75,8.895)
  rect 0.9x1.5 smd: 15(-6.985,-8.895) 16(-5.715,-8.895) 17(-4.445,-8.895) 18(-3.175,-8.895) 19(-1.905,-8.895) 20(-0.635,-8.895) 21(0.635,-8.895) 22(1.905,-8.895) 23(3.175,-8.895) 24(4.445,-8.895) 25(5.715,-8.895) 26(6.985,-8.865)
  rect 0.9x0.9 smd: 41(-2.9,-0.225) 41(-2.9,1.175) 41(-2.9,2.575) 41(-1.5,2.575) 41(-1.5,-0.225) 41(-1.5,1.175) 41(-0.1,2.575) 41(-0.1,1.175) 41(-0.1,-0.225)
  silkscreen extent -9,-9.14 9.02,16.39

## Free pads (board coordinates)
  round 1.524 hole 0.914: 1(89.467,94.238) 1(100.389,117.352) 1(104.961,99.064)
  round 0.08 smd: 55(84.514,87.126) 55(85.149,86.618) 55(85.271,117.166) 55(86.292,116.844) 55(87.15,146.964) 55(87.181,86.618) 55(87.181,116.463) 55(89.194,83.081) 55(89.213,82.173) 55(91.753,132.973) 55(114.861,93.568) 55(116.341,95.598) 55(133.577,91.767) 55(134.977,91.727)
  round 0.08 smd far side: 55(95.182,117.225) 55(101.786,126.348) 55(102.929,126.369) 55(103.056,138.18) 55(103.761,127.315) 55(104.707,127.741)

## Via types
v1: diameter 0.4, hole 0.3, Top Layer to Bottom Layer, 269 vias
v2: diameter 0.5, hole 0.3, Top Layer to Bottom Layer, 3 vias

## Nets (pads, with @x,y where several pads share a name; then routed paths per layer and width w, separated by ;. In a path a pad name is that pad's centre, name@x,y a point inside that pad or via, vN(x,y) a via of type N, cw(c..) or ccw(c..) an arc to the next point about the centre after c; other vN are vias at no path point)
$1N8318: C15.2 U5.43 | length 1.4
  Top Layer w0.254: C15.2@122.428,149.102 122.665,148.865 U5.43@122.665,147.759
$1N8986: C16.2 U5.49 | length 1.5
  Top Layer w0.254: C16.2@117.545,149.091 117.865,148.771 U5.49@117.865,147.759
$1N9039: C14.1 U5.27 | length 0.7
  Top Layer w0.254: U5.27@134.665,136.475 134.738,136.402 C14.1@135.373,136.402
$1N9091: C13.1 U5.14 | length 1.5
  Top Layer w0.254: C13.1@124.265,135.005 U5.14@124.265,136.475
$1N9142: C12.1 U5.9 | length 1.4
  Top Layer w0.254: 119.82,135.259 120.265,135.704 U5.9@120.265,136.475
$1N9192: C11.1 U5.3 | length 1.4
  Top Layer w0.254: C11.1@115.316,135.132 115.465,135.281 U5.3@115.465,136.475
$1N9241: C10.1 U5.1 | length 1.5
  Top Layer w0.254: C10.1@113.865,135.132 U5.1@113.865,136.602
$1N9341: C8.1 C10.2 C11.2 C12.2 C13.2 C14.2 C15.1 C16.1 R1.2 | length 66.2
  Top Layer w0.254: C10.2@114.3,135.132 114.613,134.819 v1(114.613,134.645) 114.926,134.958 C11.2@114.926,135.132 ; v1(116.802,149.894) 117.269,149.427 C16.1@117.269,149.367 ; v1(119.058,134.497) C12.2@119.428,134.867 ; v1(121.558,149.523) 121.617,149.523 C15.1@122.038,149.102 ; v1(123.63,132.973) 123.757,132.846 125.916,132.846 126.932,133.862 v1(127.059,133.862) ; v1(124.265,133.989) C13.2@124.265,134.556 ; v1(125.154,150.88) 126.603,150.88 R1.2@126.678,150.805 ; C14.2@135.763,136.402 v1(135.763,136.91) ; C8.1@136.711,142.99 137.457,142.244 v1(138.235,142.244)
  Bottom Layer w0.254: v1(114.613,134.645) 114.761,134.497 v1(119.058,134.497) 122.106,134.497 v1(123.63,132.973) 123.63,133.354 v1(124.265,133.989) ; v1(116.802,149.894) 121.187,149.894 v1(121.558,149.523) 123.797,149.523 v1(125.154,150.88) 135.763,140.271 v1(135.763,136.91) ; v1(127.059,133.862) 132.715,133.862 v1(135.763,136.91) ; v1(138.235,142.244) 138.235,139.382 v1(135.763,136.91)
$1N9437: R1.1 U5.37 | length 2.5
  Top Layer w0.254: R1.1@126.678,149.939 127.465,149.152 U5.37@127.465,147.759
$1N11348: R2.1 U5.38 | length 19.3
  Top Layer w0.1: R2.1@109.839,143.26 123.122,143.26 126.678,146.816 126.678,147.746 U5.38@126.665,147.759
$1N11975: R7.1 U2.3 | length 1.5
  Top Layer w0.254: U2.3@87.938,97.807 87.943,97.802 R7.1@87.943,96.322
$1N12553: R10.2 USB1.B5 | length 1.7
  Top Layer w0.254: USB1.B5@83.574,85.122 84.804,85.122 R10.2@85.157,85.475
$1N12557: R9.2 USB1.A5 | length 2
  Top Layer w0.254: USB1.A5@83.574,88.122 84.612,88.122 R9.2@85.276,88.786
$1N14416: C18.2 L1.1 U6.5 | length 7.6
  Top Layer w0.254: L1.1@89.134,86.872 89.134,89.031 88.705,89.46 88.705,92.112 88.987,92.395 89.207,92.395 C18.2@89.213,92.401 90.725,92.401 U6.5@90.784,92.46
$1N14459: C18.1 U6.6 | length 1.8
  Top Layer w0.254: C18.1@89.213,92.011 89.714,91.51 U6.6@90.784,91.51
$1N14567: C19.1 R11.1 R12.2 U6.1 | length 11.6
  Top Layer w0.254: U6.1@93.484,91.51 97.467,91.51 C19.1@98.611,90.366 101.605,90.366 R11.1@101.659,90.419 104.563,90.419 R12.2@104.58,90.437
$1N16832: C24.2 L2.1 U7.5 | length 5.3
  Top Layer w0.254: C24.2@122.995,93.662 122.174,92.841 U7.5@121.678,92.841 121.684,92.835 L2.1@125.313,92.835
$1N16833: C24.1 U7.6 | length 1.4
  Top Layer w0.254: U7.6@121.678,93.791 121.933,94.046 122.989,94.046 C24.1@122.995,94.052
$1N16834: C25.1 R14.2 R15.1 U7.1 | length 30.7
  Top Layer w0.254: U7.1@118.978,93.791 119.272,93.791 120.328,92.736 120.328,91.996 128.627,83.697 135.695,83.697 136.563,84.565 R14.2@136.563,88.317 135.547,88.317 R15.1@135.03,87.8 134.977,87.747 C25.1@134.977,85.133
$1N17349: C29.2 C30.2 C31.1 C32.1 | length 3.8
  Top Layer w0.254: C30.2@117.221,99.064 118.296,97.989 C32.1@118.296,96.688 117.385,96.688 C29.2@117.348,96.651
$1N29790: R26.2 U2.5 | length 57.9
  Top Layer w0.1: v1(78.029,137.926) 78.291,138.188 R26.2@78.291,138.763 ; U2.5@90.478,97.807 90.483,97.802 v1(90.483,96.778)
  Bottom Layer w0.1: v1(78.029,137.926) 77.91,137.807 77.91,137.494 77.781,137.366 77.781,137.094 77.91,136.966 77.91,136.694 77.781,136.566 77.781,136.294 77.91,136.166 77.91,135.894 77.781,135.766 77.781,135.494 77.91,135.366 77.91,135.094 77.781,134.966 77.781,134.694 77.91,134.566 77.91,134.294 77.781,134.166 77.781,133.894 77.91,133.766 77.91,133.494 77.781,133.366 77.781,133.094 77.91,132.966 77.91,95.889 78.164,95.635 87.942,95.635 89.085,96.778 v1(90.483,96.778)
$1N29833: R27.2 U2.6 | length 59.2
  Top Layer w0.1: v1(78.708,137.89) 78.708,138.037 R27.2@79.434,138.763 ; v1(91.748,96.778) U2.6@91.748,97.807
  Bottom Layer w0.1: v1(78.708,137.89) 78.418,137.6 78.418,137.329 78.347,137.258 78.21,137.258 78.139,137.188 78.139,136.929 78.21,136.858 78.347,136.858 78.418,136.788 78.418,136.529 78.347,136.458 78.21,136.458 78.139,136.388 78.139,136.129 78.21,136.058 78.347,136.058 78.418,135.988 78.418,135.729 78.347,135.658 78.21,135.658 78.139,135.588 78.139,135.329 78.21,135.258 78.347,135.258 78.418,135.188 78.418,134.929 78.347,134.858 78.21,134.858 78.139,134.788 78.139,134.529 78.21,134.458 78.347,134.458 78.418,134.388 78.418,134.129 78.347,134.058 78.21,134.058 78.139,133.988 78.139,133.729 78.21,133.658 78.347,133.658 78.418,133.588 78.418,133.329 78.347,133.258 78.21,133.258 78.139,133.188 78.139,132.929 78.21,132.858 78.347,132.858 78.418,132.788 78.418,132.529 78.347,132.458 78.21,132.458 78.139,132.388 78.139,132.129 78.21,132.058 78.347,132.058 78.418,131.988 78.418,131.765 78.347,131.694 78.21,131.694 78.139,131.624 78.139,131.365 78.21,131.294 78.347,131.294 78.418,131.224 78.418,130.965 78.347,130.894 78.21,130.894 78.139,130.824 78.139,130.565 78.21,130.494 78.347,130.494 78.418,130.424 78.418,130.165 78.347,130.094 78.21,130.094 78.139,130.024 78.139,129.765 78.21,129.694 78.347,129.694 78.418,129.624 78.418,99.318 80.196,97.54 90.986,97.54 v1(91.748,96.778)
$1N29916: R29.2 U2.9 | length 59.1
  Top Layer w0.1: v1(80.019,137.722) 80.374,137.722 81.415,138.763 R29.2@81.72,138.763 ; v1(94.166,99.572) 95.558,98.18 U2.9@95.558,97.807
  Bottom Layer w0.1: v1(80.019,137.722) 79.817,137.52 79.76,137.52 79.488,137.247 79.488,136.95 79.559,136.88 79.744,136.88 79.815,136.809 79.815,136.55 79.744,136.48 79.559,136.48 79.488,136.409 79.488,136.15 79.559,136.08 79.744,136.08 79.815,136.009 79.815,135.75 79.744,135.68 79.559,135.68 79.488,135.609 79.488,135.35 79.559,135.28 79.744,135.28 79.815,135.209 79.815,134.95 79.744,134.88 79.559,134.88 79.488,134.809 79.488,134.55 79.559,134.48 79.744,134.48 79.815,134.409 79.815,134.15 79.744,134.08 79.559,134.08 79.488,134.009 79.488,133.75 79.559,133.68 79.744,133.68 79.815,133.609 79.815,133.35 79.744,133.28 79.559,133.28 79.488,133.209 79.488,132.995 79.559,132.925 79.744,132.925 79.815,132.854 79.815,132.595 79.744,132.525 79.559,132.525 79.488,132.454 79.488,132.195 79.559,132.125 79.744,132.125 79.815,132.054 79.815,131.795 79.744,131.725 79.559,131.725 79.488,131.654 79.488,102.82 82.736,99.572 v1(94.166,99.572)
$1N29959: R30.2 U2.12 | length 59.5
  Top Layer w0.1: v1(80.958,137.672) 81.772,137.672 R30.2@82.863,138.763 ; v1(91.499,101.096) 98.357,101.096 99.368,100.085 U2.12@99.368,97.807
  Bottom Layer w0.1: v1(80.958,137.672) 80.538,137.672 80.186,137.32 80.186,137.31 80.142,137.266 80.142,104.325 83.371,101.096 v1(91.499,101.096)
$1N30002: R31.2 U2.23 | length 58.9
  Top Layer w0.1: v1(81.339,110.748) 101.151,110.748 102.167,109.732 U2.23@103.061,109.732 ; v1@82.228,137.672 82.915,137.672 R31.2@84.006,138.763
  Bottom Layer w0.1: v1(81.339,110.748) 80.742,111.344 80.742,126.682 80.672,126.753 80.442,126.753 80.371,126.823 80.371,127.082 80.442,127.153 80.672,127.153 80.742,127.223 80.742,127.482 80.672,127.553 80.442,127.553 80.371,127.623 80.371,127.882 80.442,127.953 80.672,127.953 80.742,128.023 80.742,128.282 80.672,128.353 80.442,128.353 80.371,128.423 80.371,128.682 80.442,128.753 80.672,128.753 80.742,128.823 80.742,129.082 80.672,129.153 80.442,129.153 80.371,129.223 80.371,129.482 80.442,129.553 80.672,129.553 80.742,129.623 80.742,129.882 80.672,129.953 80.442,129.953 80.371,130.023 80.371,130.282 80.442,130.353 80.672,130.353 80.742,130.423 80.742,130.682 80.672,130.753 80.442,130.753 80.371,130.823 80.371,131.082 80.442,131.153 80.672,131.153 80.742,131.223 80.742,131.482 80.672,131.553 80.442,131.553 80.371,131.623 80.371,131.882 80.442,131.953 80.672,131.953 80.742,132.023 80.742,132.282 80.672,132.353 80.442,132.353 80.371,132.423 80.371,132.682 80.442,132.753 80.672,132.753 80.742,132.823 80.742,133.082 80.672,133.153 80.442,133.153 80.371,133.223 80.371,133.482 80.442,133.553 80.672,133.553 80.742,133.623 80.742,133.882 80.672,133.953 80.442,133.953 80.371,134.023 80.371,134.282 80.442,134.353 80.672,134.353 80.742,134.423 80.742,135.22 80.342,135.621 80.342,136.904 80.621,137.183 81.47,137.183 81.903,137.616 v1(82.284,137.616)
$1N30085: R34.2 U2.25 | length 59.4
  Top Layer w0.1: v1@84.387,137.418 85.074,137.418 86.292,138.636 R34.2@86.292,138.763 ; v1(84.895,112.399) 85.022,112.272 85.83,112.272 85.901,112.343 85.901,112.582 85.971,112.653 86.23,112.653 86.301,112.582 86.301,112.343 86.371,112.272 86.63,112.272 86.701,112.343 86.701,112.582 86.771,112.653 87.03,112.653 87.101,112.582 87.101,112.343 87.171,112.272 87.43,112.272 87.501,112.343 87.501,112.582 87.571,112.653 87.83,112.653 87.901,112.582 87.901,112.343 87.971,112.272 88.23,112.272 88.301,112.343 88.301,112.582 88.371,112.653 88.63,112.653 88.701,112.582 88.701,112.343 88.771,112.272 89.03,112.272 89.101,112.343 89.101,112.582 89.171,112.653 89.43,112.653 89.501,112.582 89.501,112.343 89.571,112.272 U2.25@103.061,112.272
  Bottom Layer w0.1: v1(84.379,137.425) 82.355,135.401 82.355,135.08 82.426,135.009 82.792,135.009 82.863,134.939 82.863,134.68 82.792,134.609 82.426,134.609 82.355,134.539 82.355,134.28 82.426,134.209 82.782,134.209 82.852,134.139 82.852,133.88 82.782,133.809 82.426,133.809 82.355,133.739 82.355,133.48 82.426,133.409 82.791,133.409 82.861,133.339 82.861,133.08 82.791,133.009 82.426,133.009 82.355,132.939 82.355,132.68 82.426,132.609 82.782,132.609 82.852,132.539 82.852,132.28 82.782,132.209 82.426,132.209 82.355,132.139 82.355,131.88 82.426,131.809 82.827,131.809 82.897,131.739 82.897,131.48 82.827,131.409 82.426,131.409 82.355,131.339 82.355,131.08 82.426,131.009 82.853,131.009 82.924,130.939 82.924,130.68 82.853,130.609 82.426,130.609 82.355,130.539 82.355,130.28 82.426,130.209 82.898,130.209 82.969,130.139 82.969,129.88 82.898,129.809 82.426,129.809 82.355,129.739 82.355,129.525 82.426,129.454 82.905,129.454 82.976,129.383 82.976,129.125 82.905,129.054 82.426,129.054 82.355,128.983 82.355,128.725 82.426,128.654 82.905,128.654 82.976,128.583 82.976,128.325 82.905,128.254 82.426,128.254 82.047,127.875 82.047,115.247 v1(84.895,112.399)
$1N30089: R32.2 U2.24 | length 59.6
  Top Layer w0.1: v1(83.371,137.545) 83.931,137.545 R32.2@85.149,138.763 ; v1(84.641,111.764) 101.024,111.764 101.786,111.002 U2.24@103.061,111.002
  Bottom Layer w0.1: v1(83.371,137.545) 82.809,136.983 81.808,136.983 81.212,136.387 81.212,134.655 81.283,134.585 81.776,134.585 81.847,134.514 81.847,134.255 81.776,134.185 81.283,134.185 81.212,134.114 81.212,133.855 81.283,133.785 81.776,133.785 81.847,133.714 81.847,133.455 81.776,133.385 81.283,133.385 81.212,133.314 81.212,133.055 81.283,132.985 81.776,132.985 81.847,132.914 81.847,132.655 81.776,132.585 81.283,132.585 81.212,132.514 81.212,132.255 81.283,132.185 81.776,132.185 81.847,132.114 81.847,131.855 81.776,131.785 81.283,131.785 81.212,131.714 81.212,131.455 81.283,131.385 81.776,131.385 81.847,131.314 81.847,131.055 81.776,130.985 81.283,130.985 81.212,130.914 81.212,130.655 81.283,130.585 81.776,130.585 81.847,130.514 81.847,130.255 81.776,130.185 81.283,130.185 81.212,130.114 81.212,129.855 81.283,129.785 81.776,129.785 81.847,129.714 81.847,129.455 81.776,129.385 81.283,129.385 81.212,129.314 81.212,129.055 81.283,128.985 81.776,128.985 81.847,128.914 81.847,128.655 81.776,128.585 81.283,128.585 81.212,128.514 81.212,128.255 81.283,128.185 81.776,128.185 81.847,128.114 81.847,127.855 81.776,127.785 81.283,127.785 81.212,127.714 81.212,115.193 v1(84.641,111.764)
$1N30093: R28.2 U2.7 | length 59.1
  Top Layer w0.1: v1(79.34,137.799) 79.401,137.799 80.365,138.763 R28.2@80.577,138.763 ; U2.7@93.018,97.807 v1(93.018,98.81)
  Bottom Layer w0.1: v1(79.34,137.799) 78.672,137.131 78.672,136.887 78.743,136.816 78.855,136.816 78.926,136.745 78.926,136.487 78.855,136.416 78.743,136.416 78.672,136.345 78.672,136.087 78.743,136.016 78.855,136.016 78.926,135.945 78.926,135.687 78.855,135.616 78.743,135.616 78.672,135.545 78.672,135.287 78.743,135.216 78.855,135.216 78.926,135.145 78.926,134.887 78.855,134.816 78.743,134.816 78.672,134.745 78.672,134.487 78.743,134.416 78.855,134.416 78.926,134.345 78.926,134.087 78.855,134.016 78.743,134.016 78.672,133.945 78.672,133.687 78.743,133.616 78.855,133.616 78.926,133.545 78.926,133.287 78.855,133.216 78.743,133.216 78.672,133.145 78.672,132.887 78.743,132.816 78.855,132.816 78.926,132.745 78.926,132.487 78.855,132.416 78.743,132.416 78.672,132.345 78.672,132.087 78.743,132.016 78.855,132.016 78.926,131.945 78.926,131.687 78.855,131.616 78.743,131.616 78.672,131.545 78.672,131.295 78.743,131.224 78.982,131.224 79.053,131.153 79.053,130.895 78.982,130.824 78.743,130.824 78.672,130.753 78.672,130.495 78.743,130.424 78.982,130.424 79.053,130.353 79.053,130.095 78.982,130.024 78.743,130.024 78.672,129.953 78.672,100.08 79.942,98.81 v1(93.018,98.81)
$1N33205: P1.8 R35.1 | length 1.9
  Top Layer w0.1: R35.1@110.041,163.759 110.081,163.799 P1.8@110.081,165.626
$2N5507: R23.2 U1.P10 | length 20
  Top Layer w0.1: R23.2@84.185,141.101 86.8,141.101 86.906,140.995 86.906,140.807 87.522,140.191 89.742,140.191 v1(90.102,139.831)
  Top Layer w0.254: U1.P10@102.224,138.86 102.548,139.184 v1@102.548,139.196
  Bottom Layer w0.254: v1(90.102,139.831) 90.46,140.189 100.509,140.189 101.38,139.317 102.088,139.317 102.188,139.217 v1@102.569,139.217
  other v1: 102.569,139.217
$2N5509: R24.2 U1.N10 | length 23.9
  Top Layer w0.1: v1(87.816,139.789) 89.575,139.789 89.935,139.429 90.268,139.429 90.628,139.789 90.822,139.789 92.066,141.033 92.066,141.038 92.702,141.674 93.495,141.674 94.327,140.842 96.95,140.842 97.042,140.75 97.042,140.302 97.266,140.078 98.382,140.078 98.389,140.085 98.858,140.085 98.866,140.078 99.182,140.078 99.406,140.302 99.406,140.66 99.588,140.842 100.782,140.842 101.042,140.582 101.042,139.502 101.266,139.278 101.842,139.278 U1.N10@102.224,139.66
  Top Layer w0.254: R24.2@86.344,143.641 87.233,142.752 v1(88.07,142.752)
  Bottom Layer w0.1: v1(87.816,139.789) 87.562,140.043 87.562,140.668 88.27,141.376 88.27,141.8 88.197,141.873 88.197,142.117 88.07,142.244 v1(88.07,142.752)
$2N5511: R25.2 U1.R10 | length 7.9
  Top Layer w0.1: R25.2@97.595,132.517 v1(97.595,133.354) ; v1(101.024,137.672) 101.836,137.672 U1.R10@102.224,138.06
  Bottom Layer w0.1: v1(97.595,133.354) 100.876,136.635 100.876,136.823 101.024,136.971 v1(101.024,137.672)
